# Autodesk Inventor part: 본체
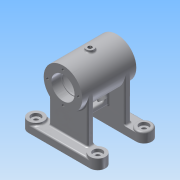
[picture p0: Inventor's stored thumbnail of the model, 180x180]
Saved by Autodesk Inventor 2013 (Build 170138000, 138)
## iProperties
Created: 2015-11
Part Number: 본체
Material: 알루미늄 6061
Document SubType Name: Modeling
Designer: Administrator
Density: 2.71 g/cm^3
Mass: 362.822 g
Surface Area: 463.591 cm^2
Volume: 133.883 cm^3
Author: Administrator
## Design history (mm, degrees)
sketch "스케치1"
  geometry: 1 further point
sketch "스케치2"
  geometry: L1 (0, 40)-(-40, 40); L2 (-40, 40)-(-40, 30); L3 (-40, 20)-(40, 20); L4 (40, 20)-(40, 30); L5 (40, 40)-(0, 40); L6 (0, -40)-(-40, -40); L7 (-40, -40)-(-40, -30); L8 (-40, -20)-(40, -20); L9 (40, -20)-(40, -30); L10 (40, -40)-(0, -40); A1 r 10 centre (-40, 30) between (-40, 40) and (-40, 20); A2 r 10 centre (40, 30) between (40, 20) and (40, 40); A3 r 10 centre (-40, -30) between (-40, -20) and (-40, -40); A4 r 10 centre (40, -30) between (40, -40) and (40, -20)
  constraints: 20 end point, 8 point on circle, 4 centre point, 4 coincident, 2 perpendicular, 2 tangent
  dimensions: "d9" = 40 distance of L1.start L1.end; "d10" = 10 distance of L1.end L2.end; "d11" = 80 distance of L3.start L3.end; "d12" = 10 distance of L3.end L4.end
extrude "돌출1" new body sketch "스케치2" distance "d13" = 10; taper "d14" = 0 deg
node "작업 평면1"
sketch "스케치3"
  geometry: L1 (40, 20)-(-40, 20) reference; L2 (-40, 40)-(40, 40) reference; L3 (-40, -20)-(40, -20) reference; L4 (40, -40)-(-40, -40) reference; C1 r 10 at (-40, 30); A1 r 10 centre (40, 30) between (40, 20) and (40, 40) reference; A2 r 10 centre (-40, 30) between (-40, 40) and (-40, 20) reference; A3 r 10 centre (-40, -30) between (-40, -20) and (-40, -40) reference; A4 r 10 centre (40, -30) between (40, -40) and (40, -20) reference; 4 further points
  constraints: 4 coincident, 3 vertical alignment, 1 centre point, 6 other
  dimensions: "d16" = 20 diameter of C1
extrude "돌출2" join sketch "스케치3" distance "d17" = 3; taper "d18" = 0 deg
sketch "스케치4"
  geometry: L1 (-40, -20)-(40, -20) reference; L2 (40, -40)-(-40, -40) reference; L3 (-40, 40)-(40, 40) reference; L4 (40, 20)-(-40, 20) reference; L5 (0, -20)-(-25, -20); L6 (-25, -20)-(-25, -28); L7 (-25, -28)-(25, -28); L8 (25, -28)-(25, -20); A1 r 10 centre (-40, -30) between (-40, -40) and (-40, -20) reference; A2 r 10 centre (-40, -30) between (-40, -20) and (-40, -40) reference; A3 r 10 centre (40, -30) between (40, -40) and (40, -20) reference; A4 r 10 centre (40, -30) between (40, -20) and (40, -40) reference; A5 r 10 centre (40, 30) between (40, 20) and (40, 40) reference; A6 r 10 centre (40, 30) between (40, 40) and (40, 20) reference; A7 r 10 centre (-40, 30) between (-40, 40) and (-40, 20) reference; A8 r 10 centre (-40, 30) between (-40, 20) and (-40, 40) reference; 1 further point
  constraints: 8 end point, 2 perpendicular, 2 point on line, 1 midpoint, 1 parallel
  dimensions: "d19" = 25 distance of L5.start L5.end; "d20" = 8 distance of L5.end L6.end; "d21" = 50 distance of L6.end L7.end
extrude "돌출3" join sketch "스케치4" distance "d22" = 58; taper "d23" = 0 deg
sketch "스케치5"
  geometry: L1 (0, 0)-(0, 68); C1 r 25 at (0, 68)
  constraints: 2 end point, 1 centre point, 1 coincident, 1 vertical
  dimensions: "d24" = 68 distance of L1.start L1.end; "d25" = 50 diameter of C1
extrude "돌출4" join sketch "스케치5" stored distance "d26" = 70; taper "d27" = 0 deg
node "작업 평면3"
sketch "스케치6"
  geometry: L1 (-25, 28)-(25, 28) reference; L2 (25, 28)-(25, 20) reference; L3 (25, 20)-(-25, 20) reference; L4 (-25, 20)-(-25, 28) reference; L5 (-25, -20)-(25, -20) reference; L6 (25, -20)-(25, -28) reference; L7 (25, -28)-(-25, -28) reference; L8 (-25, -28)-(-25, -20) reference; L9 (-25, 28)-(25, 28) reference; L10 (25, 28)-(25, 20) reference; L11 (25, 20)-(-25, 20) reference; L12 (-25, 20)-(-25, 28) reference; L13 (-25, -20)-(25, -20) reference; L14 (25, -20)-(25, -28) reference; L15 (25, -28)-(-25, -28) reference; L16 (-25, -28)-(-25, -20) reference; L17 (0, 20)-(-4, 20); L18 (-4, 20)-(-4, -20); L19 (-4, -20)-(4, -20); L20 (4, -20)-(4, 20); L21 (4, 20)-(0, 20); 1 further point
  constraints: 10 end point, 4 point on line, 2 perpendicular, 1 collinear, 1 midpoint
  dimensions: "d30" = 8 distance of L18.end L19.end
extrude "돌출5" join sketch "스케치6" stored distance "d31" = 70; taper "d32" = 0 deg
sketch "스케치7"
  geometry: L1 (-13.5, 8.5)-(-13.5, 31.5); L2 (-6.5, 31.5)-(-6.5, 8.5); A1 r 3.5 centre (-10, 31.5) between (-6.5, 31.5) and (-13.5, 31.5); A2 r 3.5 centre (-10, 8.5) between (-13.5, 8.5) and (-6.5, 8.5); 1 further point
  constraints: 4 end point, 4 point on circle, 3 tangent, 2 centre point, 1 parallel
  dimensions: "d35" = 7 diameter of A1; "d37" = 7 diameter of A2
extrude "돌출6" cut sketch "스케치7" distance "d38" = 70; taper "d39" = 0 deg
node "작업 평면7"
sketch "스케치8"
  geometry: C1 r 5 at (0, 0); 1 further point
  constraints: 1 centre point, 1 coincident
  dimensions: "d41" = 10 diameter of C1
extrude "돌출7" join sketch "스케치8" stored distance "d42" = 70; taper "d43" = 0 deg
hole "구멍2" diameter "d55" = 30; stored, may be unused: countersink angle "d59" = 90 deg, drill point angle "d61" = 0 deg; dims "d53" = 10, "d54" = 10, "d56" = 6, "d57" = 4, "d58" = 2, "d60" = 12
hole "구멍3" diameter "d64" = 30; stored, may be unused: countersink angle "d68" = 90 deg, drill point angle "d70" = 0 deg; dims "d62" = 10, "d63" = 10, "d65" = 6, "d66" = 4, "d67" = 2, "d69" = 12
sketch "스케치9"
  geometry: C1 r 14 at (0, 0); 1 further point
  constraints: 1 centre point
  dimensions: "d71" = 28 diameter of C1
extrude "돌출8" cut sketch "스케치9" distance "d72" = 2; taper "d73" = 0 deg
sketch "스케치10"
  geometry: C1 r 14 at (0, 0); 1 further point
  constraints: 1 centre point
  dimensions: "d74" = 28 diameter of C1
extrude "돌출9" cut sketch "스케치10" distance "d75" = 2; taper "d76" = 0 deg
sketch "스케치11"
  geometry: C1 r 21 at (0, 0); 1 further point
  constraints: 1 centre point
  dimensions: "d77" = 42 diameter of C1
extrude "돌출10" cut sketch "스케치11" distance "d78" = 42; taper "d79" = 0 deg
hole "구멍4" diameter "d82" = 4.917; stored, may be unused: countersink angle "d86" = 90 deg, drill point angle "d88" = 0 deg; dims "d80" = 10, "d81" = 10, "d83" = 6, "d84" = 4, "d85" = 2, "d87" = 20
sketch "스케치12"
  geometry: 2 further points
hole "구멍6" sketch "스케치12" at (0, 20) diameter "d102" = 3.242; stored, may be unused: countersink angle "d106" = 82 deg, drill point angle "d108" = 118 deg; dims "d103" = 8, "d104" = 3.023, "d105" = 2, "d107" = 10
node "작업 평면8"
sketch "스케치13"
  geometry: 1 further point
sketch "스케치14"
  geometry: L1 (81.881, 40.033)-(81.881, 16.238); L2 (81.881, 16.238)-(37.794, 16.238); L3 (37.794, 16.238)-(37.794, 40.033); L4 (37.794, 40.033)-(81.881, 40.033); 1 further point
  constraints: 2 other
feature "엠보싱1" sketch "스케치14" dims "d113" = 0.5, "d114" = 0
fillet "모깎기1" dims "d115" = 2
fillet "모깎기2" dims "d116" = 2
fillet "모깎기3" dims "d117" = 2
fillet "모깎기4" dims "d118" = 2
fillet "모깎기5" dims "d119" = 2
hole "구멍7" diameter "d122" = 6; stored, may be unused: countersink angle "d126" = 82 deg, drill point angle "d128" = 0 deg; dims "d120" = 10, "d121" = 10, "d123" = 8, "d124" = 12, "d125" = 4, "d127" = 9
sketch "스케치15"
  geometry: C1 r 3 at (0, 0); 1 further point
  constraints: 1 centre point
  dimensions: "d129" = 6 diameter of C1
extrude "돌출11" cut sketch "스케치15" distance "d130" = 42; taper "d131" = 0 deg
fillet "모깎기6" dims "d132" = 0.3
hole "구멍8" diameter "d141" = 6; stored, may be unused: countersink angle "d145" = 82 deg, drill point angle "d147" = 0 deg; dims "d139" = 10, "d140" = 10, "d142" = 8, "d143" = 12, "d144" = 4, "d146" = 9
hole "구멍9" diameter "d150" = 6; stored, may be unused: countersink angle "d154" = 82 deg, drill point angle "d156" = 0 deg; dims "d148" = 10, "d149" = 10, "d151" = 8, "d152" = 12, "d153" = 4, "d155" = 9
hole "구멍10" diameter "d159" = 6; stored, may be unused: countersink angle "d163" = 82 deg, drill point angle "d165" = 0 deg; dims "d157" = 10, "d158" = 10, "d160" = 8, "d161" = 12, "d162" = 4, "d164" = 9
fillet "모깎기7" dims "d166" = 2
fillet "모깎기9" dims "d168" = 2
fillet "모깎기10" dims "d169" = 2
fillet "모깎기11" dims "d170" = 0.3
hole "구멍11" diameter "d176" = 4.917; stored, may be unused: countersink angle "d180" = 82 deg, drill point angle "d182" = 0 deg; dims "d174" = 10, "d175" = 10, "d177" = 12, "d178" = 12, "d179" = 4, "d181" = 12
hole "구멍12" diameter "d185" = 4.917; stored, may be unused: countersink angle "d189" = 82 deg, drill point angle "d191" = 0 deg; dims "d183" = 10, "d184" = 10, "d186" = 12, "d187" = 12, "d188" = 4, "d190" = 12
node "솔리드1"
mirror "대칭1"
pattern_circular "원형 패턴2" dims angle "d110" = 360 deg
mirror "대칭2"
pattern_linear "직사각형 패턴1" dims "d135" = -80
pattern_linear "직사각형 패턴2"
pattern_circular "원형 패턴3" dims angle "d172" = 360 deg
node "절단 모서리 투영1"
node "절단 모서리 투영2"
node "절단 모서리 투영3"
node "절단 모서리 투영4"
